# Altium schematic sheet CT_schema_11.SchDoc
size 146 x 119 mm
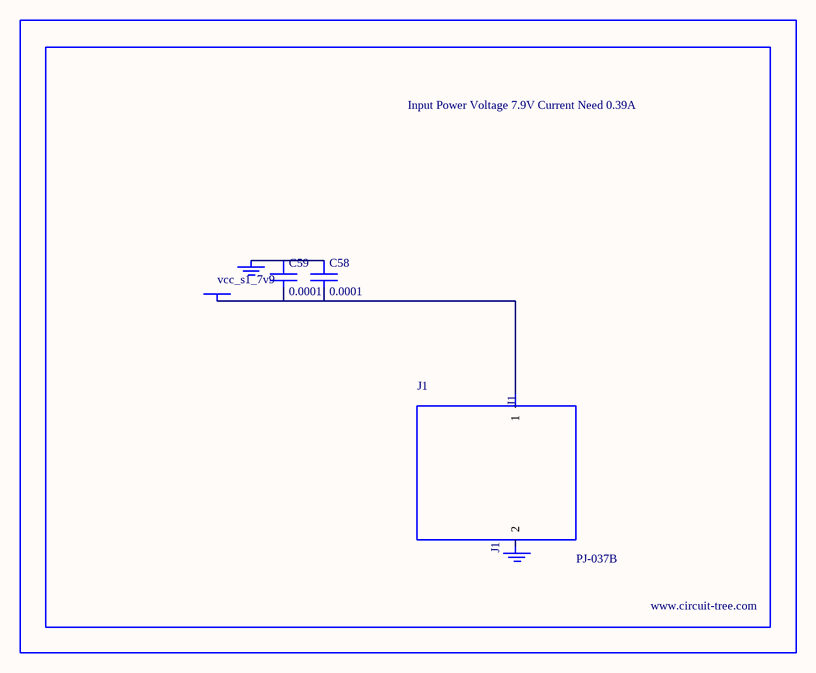
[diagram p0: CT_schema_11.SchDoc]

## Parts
BORDER10  (no value)
C58  0.0001  [EXV-9H]
C59  0.0001  [EXV-9H]
GND_INSTANCE_10_0  (no value)
GND_INSTANCE_10_1  (no value)
J1  PJ-037B  [PJ-037B_PACKAGE]
POWER_INSTANCE_10_0  vcc_s1_7v9

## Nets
NetC58_1: C58.1 C59.1 GND_INSTANCE_10_0.0(GND)
NetC58_2: C58.2 C59.2 J1.1 POWER_INSTANCE_10_0.0(PWR)

Not connected (* = marked no-connect by the designer): GND_INSTANCE_10_1 0(GND); J1 2

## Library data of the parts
BORDER10 = BORDER_PAGE10
C58 C59 = EDK107M035A9HAA
GND_INSTANCE_10_0 GND_INSTANCE_10_1 = GND
POWER_INSTANCE_10_0 = PWR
